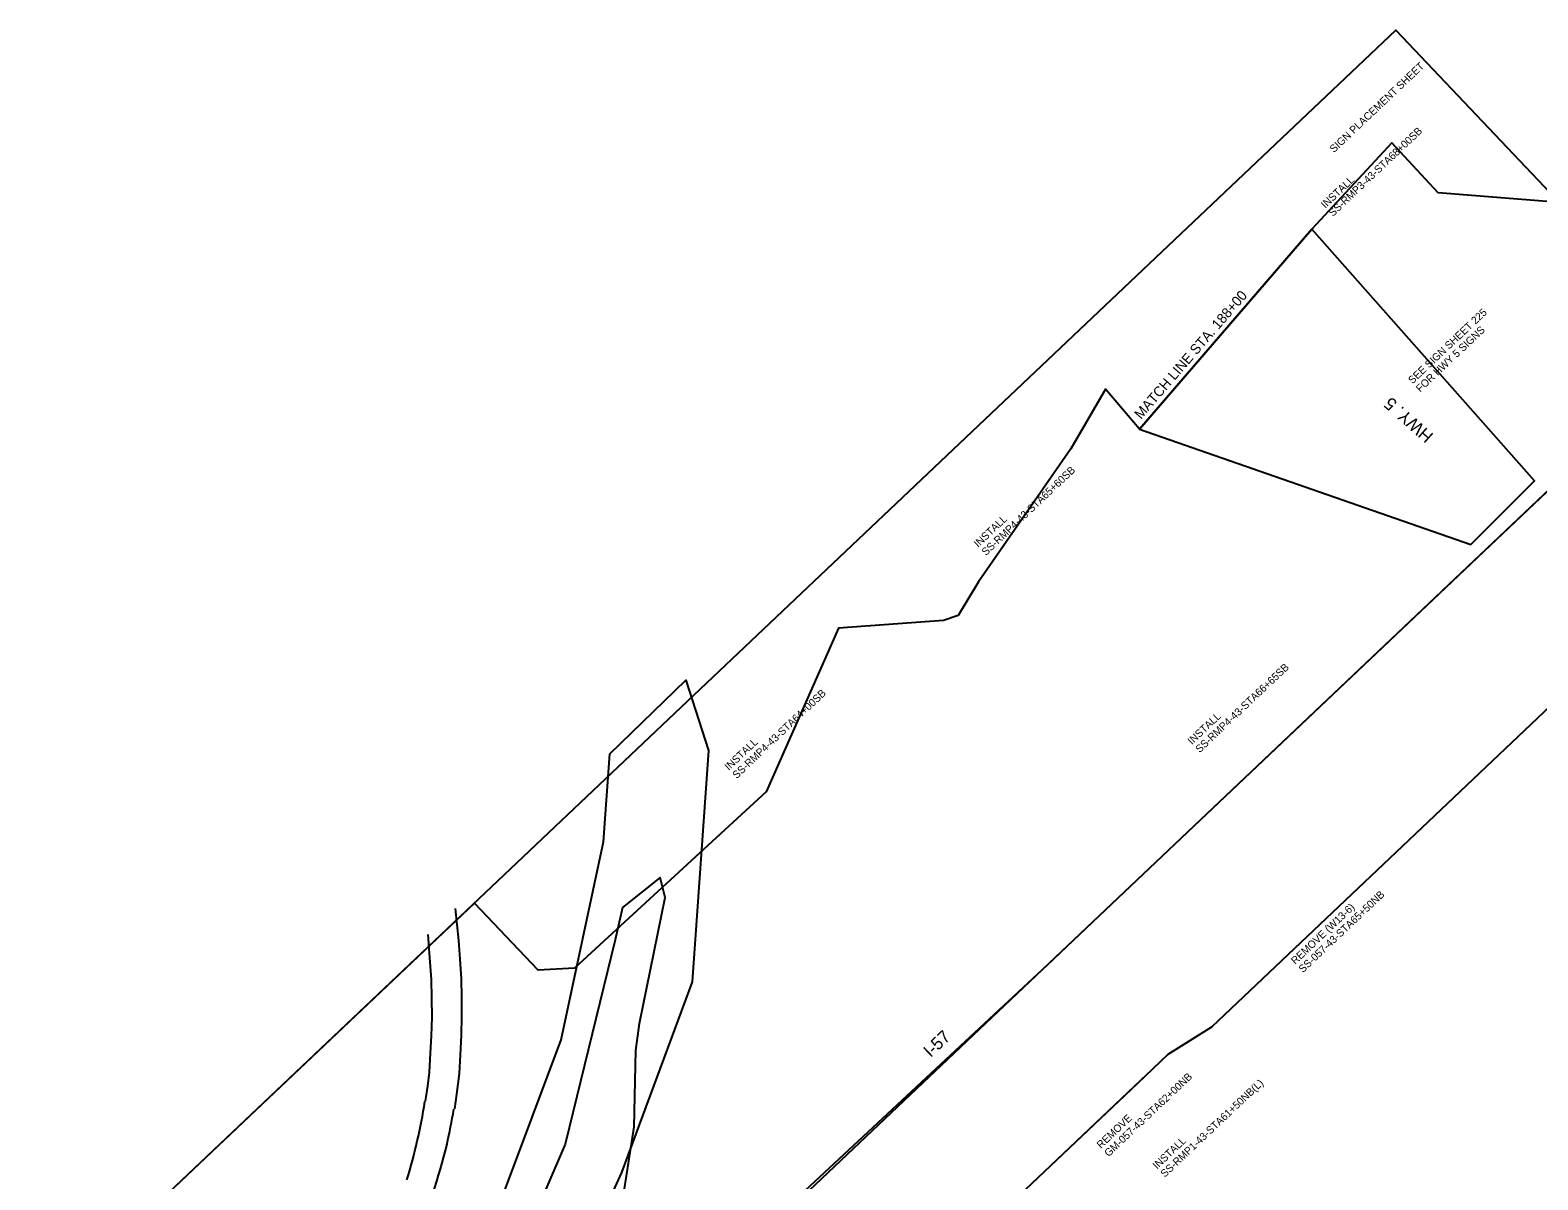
# Model space of a CAD drawing. Extents: x 1289840 to 1295361, y 220865 to 226414.
# Drawn here: x 1291900 to 1293102, y 223498 to 224415 of the extents above; entities that cross this region are included whole.
import ezdxf

# ---------------------------------------------------------------- set-up
doc = ezdxf.new("R2010")
doc.units = 0
for name, color, linetype in [('5', 7, 'Continuous'), ('Plan Notes', 7, 'Continuous'), ('R_Annotation', 7, 'Continuous'), ('R_Border', 7, 'Continuous'), ('R_No Plot', 7, 'Continuous'), ('R_Proposed Road', 7, 'Continuous'), ('S_EDGE_PAVEMENT', 7, 'Continuous')]:
    doc.layers.add(name, color=color, linetype=linetype)

msp = doc.modelspace()

# ---------------------------------------------------------------- linework, layer by layer
msp.add_lwpolyline([(1292980.7, 223090.1), (1292443.5, 222809.8), (1291900.1, 223383.1), (1292988.8, 224414.9), (1293451.5, 223926.8), (1293499.2, 223784), (1293629.8, 223673.9), (1293562.5, 223543.2), (1293152.7, 223154.8)], close=True)
for points in [[(1292371.2, 223352.9), (1292711, 223669.6), (1292746.9, 223703.6), (1293233.5, 224164.8), (1293320.5, 224073), (1293301.6, 224055.7), (1293004.1, 223773.8), (1292841.8, 223619.9), (1292807, 223598), (1292782.7, 223574.9), (1292405.6, 223217.5)], [(1292254, 223424.4), (1292323.5, 223609.8), (1292357.2, 223767.5), (1292362.3, 223837.7), (1292422.7, 223896.5), (1292440.9, 223840.4), (1292427.8, 223656), (1292371.4, 223503.8), (1292262, 223263.1)]]:
    msp.add_lwpolyline(points)
at = {"layer": '5'}
msp.add_line((1292784.3, 224096.8), (1292921.7, 224256.2), dxfattribs=at)
at = {"layer": 'R_No Plot'}
msp.add_lwpolyline([(1293119.1, 224277.5), (1293022.5, 224285.3), (1292985.6, 224325), (1292921.7, 224256.2), (1292784.3, 224096.8), (1292757.4, 224128.5), (1292729.6, 224081), (1292656.2, 223974.9), (1292639.9, 223948.2), (1292628.1, 223944), (1292544.4, 223938), (1292486.9, 223807.4), (1292333.9, 223666.7), (1292305.2, 223665.2), (1292254.4, 223718.8), (1291900.1, 223383.1)], dxfattribs=at)
for points in [[(1292784.3, 224096.8), (1293048.4, 224004.7), (1293099.3, 224055.4), (1292921.7, 224256.2)], [(1292279.8, 223247.1), (1292348.1, 223325.6), (1292381.6, 223540.4), (1292382.9, 223601.3), (1292385.8, 223622.6), (1292406.3, 223723.1), (1292402.3, 223739.1), (1292372.3, 223715.3), (1292366.5, 223689.4), (1292326.7, 223526.6), (1292230, 223301.4), (1292141.3, 223165.4), (1292125.9, 223144.9), (1292149.4, 223120), (1292282.3, 223245.3)]]:
    msp.add_lwpolyline(points, close=True, dxfattribs=at)
at = {"layer": 'R_Proposed Road'}
for p, q in [((1292348.1, 223325.6), (1293228.9, 224160.4)), ((1292405.6, 223217.5), (1292790.6, 223582.4))]:
    msp.add_line(p, q, dxfattribs=at)
at = {"layer": 'S_EDGE_PAVEMENT'}
for points in [[(1292238.8, 223714.4), (1292241.5, 223689), (1292242.6, 223674.1), (1292243.7, 223658.4), (1292244, 223643.4), (1292244, 223628.4), (1292243.6, 223613.4), (1292242.9, 223597.8), (1292242.1, 223582.9), (1292240.1, 223566.4), (1292238.4, 223554.6)], [(1292217.1, 223693.8), (1292218.8, 223671.6), (1292219.8, 223657.8), (1292220.1, 223642.8), (1292220.2, 223627.8), (1292219.8, 223612.8), (1292219.1, 223599), (1292218.1, 223584), (1292216.8, 223572.6), (1292215.1, 223560.7)]]:
    msp.add_lwpolyline(points, dxfattribs=at)
for centre, major_axis, ratio, start_param, end_param in [((1291752.7, 223634.1), (73.9, 462.7), 0.998708, 4.575942, 4.712822), ((1291751.6, 223633.9), (390.2, 300.8), 0.99998, 5.406547, 5.464075), ((1291655.9, 223672), (194, 562.3), 0.999724, 4.522474, 4.797294)]:
    msp.add_ellipse(centre, major_axis=major_axis, ratio=ratio, start_param=start_param, end_param=end_param, dxfattribs=at)

# ---------------------------------------------------------------- texts
at = {"layer": 'Plan Notes'}
for s, height, rotation, p in [('MATCH LINE STA. 188+00', 8, 49.2392, (1292785.6, 224104.1)), ('HWY. 5', 10, 138.4636, (1293019.4, 224092.4)), ('I-57', 10, 43.4636, (1292617.9, 223595.1))]:
    msp.add_text(s, height=height, rotation=rotation, dxfattribs=at).set_placement(p)
at = {"layer": 'R_Annotation'}
for s, p in [('SS-RMP3-43-STA68+00SB', (1292938.6, 224265.9)), ('INSTALL', (1292932.5, 224272.4)), ('SEE SIGN SHEET 225', (1293002, 224132.4)), ('FOR HWY 5 SIGNS', (1293008.2, 224125.8)), ('SS-RMP4-43-STA65+60SB', (1292662, 223995.4)), ('INSTALL', (1292655.8, 224002)), ('SS-RMP4-43-STA66+65SB', (1292832.4, 223838.2)), ('SS-RMP4-43-STA64+00SB', (1292463.3, 223817.5)), ('INSTALL', (1292826.2, 223844.7)), ('INSTALL', (1292457.1, 223824.1)), ('SS-057-43-STA65+50NB', (1292914.7, 223662.8)), ('REMOVE (W13-6)', (1292908.6, 223669.4)), ('GM-057-43-STA62+00NB', (1292759.8, 223516)), ('SS-RMP1-43-STA61+50NB(L)', (1292804.6, 223499.6)), ('REMOVE', (1292753.7, 223522.6)), ('INSTALL', (1292798.4, 223506.1))]:
    msp.add_text(s, height=6, rotation=43.4387, dxfattribs=at).set_placement(p)
at = {"layer": 'R_Border'}
msp.add_text('SIGN PLACEMENT SHEET', height=6, rotation=43.4654, dxfattribs=at).set_placement((1292939.4, 224316.8))

doc.saveas('drawing.dxf')
